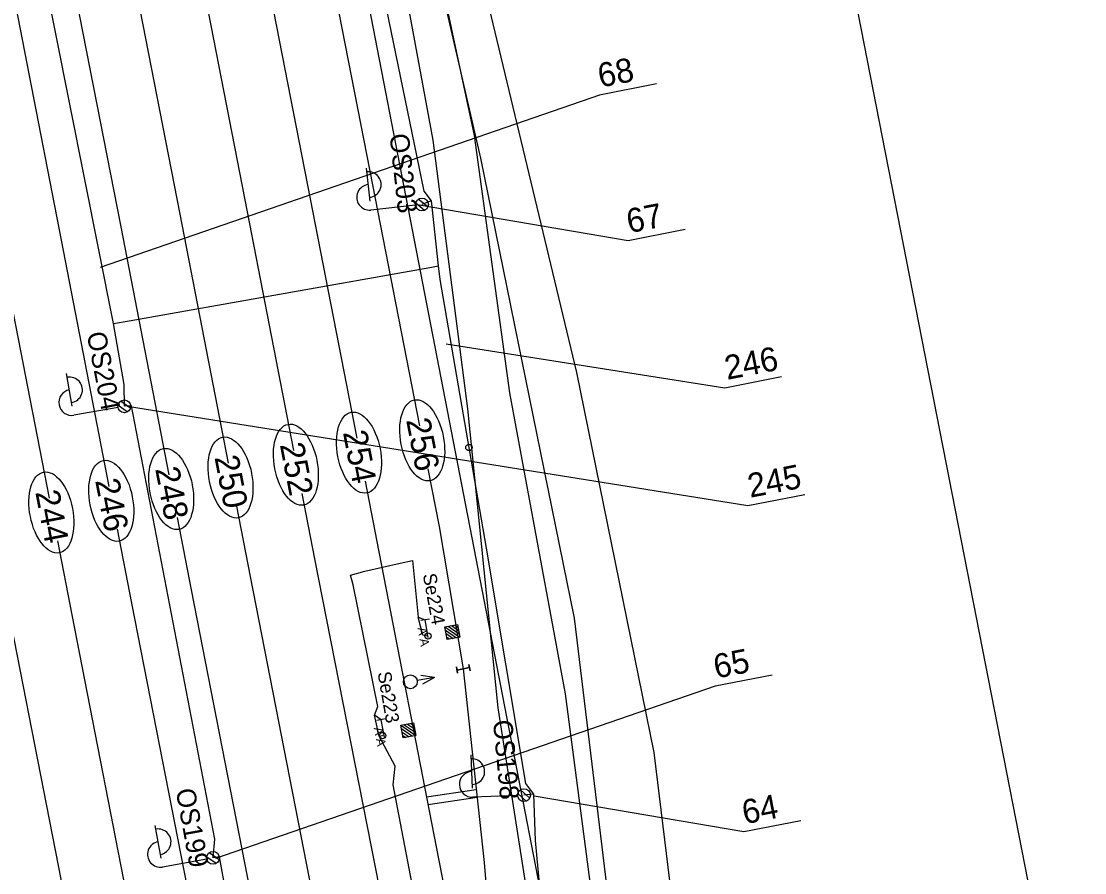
# Model space of a CAD drawing. Extents: x -545846 to -545044, y -1122650 to -1119108.
# Drawn here: x -545438.4 to -545355.4, y -1120101.7 to -1120035.3 of the extents above; entities that cross this region are included whole.
import ezdxf

# ---------------------------------------------------------------- set-up
doc = ezdxf.new("R2010")
doc.units = 0
for name, color, linetype in [('osvětlené plochy-hodnota-obrys', 7, 'Continuous'), ('so180602', 7, 'Continuous'), ('Vrstva 1', 7, 'Continuous'), ('Vrstva 10', 7, 'Continuous'), ('Vrstva 2', 7, 'Continuous'), ('Vrstva 25', 7, 'Continuous'), ('Vrstva 26', 7, 'Continuous'), ('Vrstva 27', 7, 'Continuous'), ('Vrstva 28 - zabzar', 7, 'Continuous'), ('Vrstva 3', 7, 'Continuous'), ('Vrstva 3 - Lisy - Pocitaci body', 7, 'Continuous'), ('Vrstva 35', 7, 'Continuous'), ('Vrstva 50', 7, 'Continuous'), ('Vrstva 51', 7, 'Continuous'), ('Vrstva 6 - Navesti', 7, 'Continuous'), ('Vrstva 62', 7, 'Continuous'), ('Vrstva 63', 7, 'Continuous'), ('Vrstva 7', 7, 'Continuous')]:
    doc.layers.add(name, color=color, linetype=linetype)

msp = doc.modelspace()

# ---------------------------------------------------------------- linework, layer by layer
at = {"layer": 'osvětlené plochy-hodnota-obrys'}
msp.add_lwpolyline([(-545520.965, -1119506.473), (-545505.641, -1119546.718), (-545397.928, -1120102.854)], dxfattribs=at)
at = {"layer": 'Vrstva 1'}
for points in [[(-545504.044, -1119675.302), (-545496.761, -1119712.409), (-545491.629, -1119738.674), (-545486.648, -1119764.117), (-545480.232, -1119797.005), (-545475.32, -1119822.26), (-545468.387, -1119857.799), (-545462.995, -1119885.431), (-545456.767, -1119917.378), (-545451.556, -1119944.051), (-545446.589, -1119969.431), (-545441.08, -1119997.674), (-545435.958, -1120023.865), (-545430.59, -1120051.32), (-545426.848, -1120070.672)], [(-545508.299, -1119678.306), (-545501.407, -1119713.415), (-545496.342, -1119739.402), (-545491.315, -1119765.122), (-545484.912, -1119797.951), (-545479.98, -1119823.279), (-545473.036, -1119858.809), (-545467.634, -1119886.502), (-545461.421, -1119918.347), (-545456.183, -1119945.113), (-545451.228, -1119970.493), (-545445.726, -1119998.726), (-545440.633, -1120024.762), (-545435.234, -1120052.378), (-545431.515, -1120071.58)], [(-545512.748, -1119680.062), (-545506.035, -1119714.374), (-545500.986, -1119740.293), (-545495.973, -1119766.064), (-545489.561, -1119798.976), (-545484.629, -1119824.29), (-545477.718, -1119859.753), (-545472.311, -1119887.471), (-545466.084, -1119919.335), (-545460.871, -1119946.033), (-545455.911, -1119971.399), (-545450.381, -1119999.679), (-545445.286, -1120025.774), (-545439.892, -1120053.375), (-545436.176, -1120072.488)], [(-545479.013, -1119699.159), (-545472.017, -1119734.995), (-545467.162, -1119760.064), (-545460.784, -1119792.802), (-545455.806, -1119818.056), (-545448.881, -1119853.558), (-545443.471, -1119881.241), (-545437.182, -1119913.498), (-545431.961, -1119940.155), (-545427.07, -1119965.242), (-545421.654, -1119993.224), (-545416.453, -1120019.834), (-545411.166, -1120046.971), (-545407.29, -1120066.864)], [(-545483.875, -1119700.285), (-545476.969, -1119735.847), (-545472.054, -1119761.115), (-545465.667, -1119793.733), (-545460.717, -1119819.165), (-545453.82, -1119854.518), (-545448.388, -1119882.153), (-545442.084, -1119914.383), (-545436.889, -1119940.99), (-545431.967, -1119966.286), (-545426.487, -1119994.319), (-545421.316, -1120020.9), (-545416.017, -1120048.076), (-545412.173, -1120067.814)], [(-545488.738, -1119701.593), (-545481.884, -1119736.765), (-545476.934, -1119762.146), (-545470.573, -1119794.819), (-545465.63, -1119820.165), (-545458.721, -1119855.563), (-545453.285, -1119883.263), (-545446.999, -1119915.438), (-545441.825, -1119942.011), (-545436.871, -1119967.298), (-545431.396, -1119995.476), (-545426.21, -1120021.976), (-545420.907, -1120049.228), (-545417.117, -1120068.777)], [(-545493.359, -1119705.369), (-545486.994, -1119737.853), (-545482.067, -1119763.163), (-545475.678, -1119795.841), (-545470.702, -1119821.285), (-545463.786, -1119856.655), (-545458.346, -1119884.478), (-545452.087, -1119916.549), (-545446.9, -1119943.082), (-545441.956, -1119968.347), (-545436.441, -1119996.626), (-545431.336, -1120022.902), (-545425.977, -1120050.333), (-545422.212, -1120069.769)], [(-545406.638, -1120070.213), (-545405.761, -1120074.712), (-545403.865, -1120085.82), (-545402.244, -1120100.926), (-545401.108, -1120114.416)], [(-545411.521, -1120071.164), (-545410.602, -1120075.884), (-545405.788, -1120100.651), (-545402.889, -1120115.448)], [(-545416.468, -1120072.127), (-545415.477, -1120077.238), (-545410.442, -1120102.898), (-545406.476, -1120123.181), (-545402.803, -1120143.109), (-545400.596, -1120164.815), (-545400.596, -1120181.651), (-545401.294, -1120192.943)], [(-545421.563, -1120073.119), (-545420.496, -1120078.625), (-545415.445, -1120104.449), (-545411.604, -1120124.066), (-545408, -1120142.528), (-545405.428, -1120157.949)], [(-545426.2, -1120074.022), (-545425.112, -1120079.647), (-545420.052, -1120105.492), (-545416.231, -1120125.122), (-545412.44, -1120144.547), (-545409.571, -1120160.021), (-545407.191, -1120182.024), (-545406.89, -1120192.899), (-545406.905, -1120196.005)], [(-545430.866, -1120074.93), (-545429.748, -1120080.704), (-545424.708, -1120106.469), (-545420.893, -1120126.013), (-545417.075, -1120145.62), (-545413.032, -1120166.33), (-545410.27, -1120183.003), (-545408.743, -1120196.073)], [(-545435.525, -1120075.838), (-545434.405, -1120081.599), (-545429.378, -1120107.352), (-545425.561, -1120126.873), (-545421.731, -1120146.486), (-545417.535, -1120168.115), (-545415.459, -1120178.849), (-545413.975, -1120187.465)], [(-545440.228, -1120076.753), (-545439.131, -1120082.41), (-545434.086, -1120108.231), (-545430.241, -1120127.909), (-545426.423, -1120147.488), (-545422.179, -1120169.181), (-545418.498, -1120187.953)]]:
    msp.add_lwpolyline(points, dxfattribs=at)
for centre in [(-545407.071, -1120067.99), (-545412.004, -1120068.946), (-545416.929, -1120069.89), (-545422.027, -1120070.887), (-545426.656, -1120071.785), (-545431.335, -1120072.71), (-545436.005, -1120073.616)]:
    msp.add_ellipse(centre, major_axis=(0.614, -3.151), ratio=0.521067, dxfattribs=at)
at = {"layer": 'Vrstva 10'}
msp.add_line((-545554.372, -1119108.31), (-545292.195, -1120447.895), dxfattribs=at)
at = {"layer": 'Vrstva 25'}
for p, q in [((-545411.145, -1120049.319), (-545411.427, -1120046.735)), ((-545406.633, -1120049.772), (-545407.379, -1120049.173)), ((-545407.59, -1120049.636), (-545411.069, -1120050.015)), ((-545406.896, -1120050.041), (-545407.582, -1120049.49)), ((-545434.373, -1120065.333), (-545434.824, -1120062.772)), ((-545429.84, -1120065.489), (-545430.624, -1120064.939)), ((-545430.804, -1120065.416), (-545434.251, -1120066.022)), ((-545430.085, -1120065.774), (-545430.806, -1120065.27)), ((-545403.159, -1120095.138), (-545403.262, -1120092.54)), ((-545399.634, -1120095.699), (-545403.131, -1120095.838)), ((-545398.969, -1120096.151), (-545399.615, -1120095.554)), ((-545398.688, -1120095.9), (-545399.391, -1120095.251)), ((-545427.451, -1120100.6), (-545427.916, -1120098.042)), ((-545423.882, -1120100.662), (-545427.325, -1120101.288)), ((-545423.161, -1120101.017), (-545423.884, -1120100.516)), ((-545422.917, -1120100.73), (-545423.704, -1120100.185))]:
    msp.add_line(p, q, dxfattribs=at)
for centre in [(-545407.093, -1120049.582), (-545407.093, -1120049.582), (-545430.312, -1120065.329), (-545430.312, -1120065.329), (-545399.134, -1120095.679), (-545399.134, -1120095.679), (-545423.39, -1120100.573), (-545423.39, -1120100.573)]:
    msp.add_circle(centre, 0.5, dxfattribs=at)
for centre, start, end in [((-545411.274, -1120048.026), 275.51472, 96.91987), ((-545411.178, -1120049.021), 96.2173, 276.2173), ((-545434.586, -1120064.051), 279.2814, 100.68655), ((-545434.425, -1120065.038), 99.98397, 279.98397), ((-545403.198, -1120093.839), 271.57038, 92.97552), ((-545403.171, -1120094.838), 92.27295, 272.27295), ((-545427.671, -1120099.318), 279.60078, 101.00593), ((-545427.504, -1120100.305), 100.30335, 280.30335)]:
    msp.add_arc(centre, 1, start, end, dxfattribs=at)
at = {"layer": 'Vrstva 26'}
for points in [[(-545416.465, -1119997.823), (-545416.35, -1120000.23), (-545412.42, -1120021.84), (-545406.945, -1120048.545), (-545406.368, -1120049.305), (-545407.093, -1120049.582)], [(-545419.408, -1120146.037), (-545419.607, -1120144.864), (-545417.984, -1120144.721), (-545414.909, -1120144.169), (-545418.585, -1120124.133), (-545422.884, -1120100.485), (-545423.39, -1120100.573), (-545423.256, -1120099.117), (-545429.764, -1120065.297), (-545430.312, -1120065.329), (-545430.316, -1120063.627), (-545431.155, -1120058.861), (-545436.816, -1120030.49), (-545441.618, -1120005.901), (-545442.588, -1120002.676)], [(-545406.368, -1120049.305), (-545405.816, -1120054.372), (-545405.7, -1120055.44), (-545402.08, -1120076.41), (-545399.016, -1120094.766), (-545398.394, -1120095.592), (-545399.134, -1120095.679)], [(-545431.155, -1120058.861), (-545429.949, -1120058.671), (-545406.47, -1120054.49), (-545405.816, -1120054.372)], [(-545431.155, -1120058.861), (-545429.949, -1120058.671), (-545406.47, -1120054.49)], [(-545398.394, -1120095.592), (-545398.25, -1120099.22), (-545395.83, -1120125.2), (-545394.03, -1120140.6), (-545393.889, -1120142.062), (-545393.145, -1120142.85), (-545393.979, -1120142.941)]]:
    msp.add_lwpolyline(points, dxfattribs=at)
at = {"layer": 'Vrstva 27'}
for p, q in [((-545406.616, -1120083.285), (-545406.624, -1120083.235)), ((-545410.155, -1120091.055), (-545410.165, -1120091.005))]:
    msp.add_line(p, q, dxfattribs=at)
for centre in [(-545406.62, -1120083.26), (-545410.16, -1120091.03)]:
    msp.add_circle(centre, 0.25, dxfattribs=at)
at = {"layer": 'Vrstva 28 - zabzar'}
for p, q in [((-545410.27, -1120089.79), (-545410.79, -1120089.43)), ((-545410.42, -1120091.07), (-545410.16, -1120091.03))]:
    msp.add_line(p, q, dxfattribs=at)
for points in [[(-545400.44, -1120142.19), (-545400.3, -1120141.39), (-545401.05, -1120141.27), (-545401.69, -1120138.45), (-545401.85, -1120137.24), (-545402.58, -1120132.35), (-545404.02, -1120124.35), (-545404.09, -1120123.79), (-545405.15, -1120117.55), (-545405.56, -1120115.55), (-545405.9, -1120112.13), (-545406.95, -1120107.38), (-545409.35, -1120094.87), (-545409.17, -1120093.41), (-545410.42, -1120091.07), (-545410.79, -1120089.43), (-545410.53, -1120088.75), (-545412.47, -1120079.27), (-545412.67, -1120078.51), (-545411.56, -1120078.19), (-545408.79, -1120077.57), (-545407.82, -1120077.37), (-545407.38, -1120081.8), (-545406.84, -1120082)], [(-545406.62, -1120083.26), (-545407.02, -1120083.19), (-545407.38, -1120081.8)]]:
    msp.add_lwpolyline(points, dxfattribs=at)
at = {"layer": 'Vrstva 3'}
for p, q in [((-545404.308, -1120086.161), (-545404.404, -1120085.67)), ((-545404.404, -1120085.671), (-545404.308, -1120086.161)), ((-545403.374, -1120085.724), (-545404.356, -1120085.916)), ((-545404.356, -1120085.916), (-545403.374, -1120085.724)), ((-545403.422, -1120085.479), (-545403.326, -1120085.969)), ((-545403.326, -1120085.97), (-545403.422, -1120085.479)), ((-545406.1, -1120086.506), (-545407.46, -1120086.738)), ((-545406.1, -1120086.506), (-545407.178, -1120086.34)), ((-545406.1, -1120086.506), (-545407.062, -1120087.02))]:
    msp.add_line(p, q, dxfattribs=at)
msp.add_circle((-545407.995, -1120086.828), 0.542, dxfattribs=at)
at = {"layer": 'Vrstva 3 - Lisy - Pocitaci body'}
for p, q in [((-545404.777, -1120082.446), (-545404.235, -1120082.83)), ((-545404.516, -1120082.402), (-545404.28, -1120082.569)), ((-545405.3, -1120082.535), (-545404.146, -1120083.353)), ((-545405.255, -1120082.797), (-545404.407, -1120083.397)), ((-545405.211, -1120083.058), (-545404.669, -1120083.442)), ((-545405.039, -1120082.491), (-545404.19, -1120083.092)), ((-545405.166, -1120083.32), (-545404.93, -1120083.487)), ((-545408.737, -1120090.23), (-545407.565, -1120091.021)), ((-545408.686, -1120090.49), (-545407.825, -1120091.071)), ((-545408.636, -1120090.751), (-545408.085, -1120091.122)), ((-545408.477, -1120090.179), (-545407.615, -1120090.761)), ((-545408.216, -1120090.129), (-545407.666, -1120090.5)), ((-545407.956, -1120090.078), (-545407.716, -1120090.24)), ((-545408.585, -1120091.011), (-545408.345, -1120091.173))]:
    msp.add_line(p, q, dxfattribs=at)
for points in [[(-545404.314, -1120082.367), (-545404.146, -1120083.353), (-545405.132, -1120083.521), (-545405.3, -1120082.535)], [(-545407.755, -1120090.039), (-545407.565, -1120091.021), (-545408.546, -1120091.212), (-545408.737, -1120090.23)]]:
    msp.add_lwpolyline(points, close=True, dxfattribs=at)
at = {"layer": 'Vrstva 35'}
msp.add_lwpolyline([(-545412.67, -1120078.51), (-545411.56, -1120078.19), (-545408.79, -1120077.57), (-545407.82, -1120077.37)], dxfattribs=at)
at = {"layer": 'Vrstva 50'}
msp.add_line((-545403.45, -1120068.543), (-545403.4, -1120068.543), dxfattribs=at)
msp.add_circle((-545403.425, -1120068.543), 0.25, dxfattribs=at)
at = {"layer": 'Vrstva 51'}
for points in [[(-545474.36, -1119688.255), (-545466.579, -1119732.11), (-545462.51, -1119756.655), (-545455.831, -1119789.993), (-545450.917, -1119814.901), (-545443.717, -1119850.687), (-545439.158, -1119879.07), (-545432.576, -1119913.186), (-545426.875, -1119936.671), (-545422.743, -1119962.506), (-545418.335, -1119990.017), (-545411.428, -1120016.49), (-545406.245, -1120044.568), (-545403.533, -1120065.521), (-545401.184, -1120088.868), (-545397.016, -1120115.443), (-545395.196, -1120135.679), (-545394.057, -1120143.256), (-545386.488, -1120187.748)], [(-545470.7, -1119687.746), (-545464.137, -1119731.581), (-545459.972, -1119755.883), (-545452.874, -1119789.329), (-545448.102, -1119814.108), (-545441.139, -1119850.218), (-545435.794, -1119878.29), (-545429.367, -1119912.848), (-545423.033, -1119935.797), (-545419.144, -1119961.66), (-545414.863, -1119988.762), (-545403.007, -1120044.19), (-545400.258, -1120064.288), (-545395.915, -1120087.784), (-545392.445, -1120114.396), (-545391.179, -1120135.428), (-545389.936, -1120142.632), (-545383.231, -1120188.01)]]:
    msp.add_lwpolyline(points, dxfattribs=at)
at = {"layer": 'Vrstva 6 - Navesti'}
for p, q in [((-545406.495, -1120081.941), (-545407.185, -1120082.059)), ((-545406.607, -1120083.366), (-545406.84, -1120082)), ((-545409.926, -1120089.723), (-545410.614, -1120089.857)), ((-545410.006, -1120091.151), (-545410.27, -1120089.79))]:
    msp.add_line(p, q, dxfattribs=at)
at = {"layer": 'Vrstva 62'}
for points in [[(-545423.216, -1119917.425), (-545425.626, -1119923.902), (-545421.66, -1119936.357), (-545417.987, -1119968.93), (-545408.636, -1120019.429), (-545402.531, -1120045.967), (-545395.226, -1120081.877), (-545392.76, -1120102.085), (-545388.408, -1120138.929), (-545385.069, -1120161.88), (-545380.677, -1120185.181), (-545377.636, -1120190.956), (-545375.6, -1120199.999)], [(-545371.516, -1120199.999), (-545381.387, -1120154.552), (-545388.984, -1120092.348), (-545395.017, -1120062.684), (-545403.862, -1120025.812), (-545411.302, -1119985.582), (-545417.876, -1119943.114), (-545420.973, -1119925.302), (-545417.81, -1119919.208)]]:
    msp.add_lwpolyline(points, dxfattribs=at)
at = {"layer": 'Vrstva 63'}
for p, q in [((-545388.788, -1120040.176), (-545393.232, -1120041.04)), ((-545393.232, -1120041.04), (-545432.195, -1120054.508)), ((-545391.007, -1120052.41), (-545407.3, -1120049.643)), ((-545386.563, -1120051.546), (-545391.007, -1120052.41)), ((-545383.472, -1120063.908), (-545405.197, -1120060.483)), ((-545379.027, -1120063.044), (-545383.472, -1120063.908)), ((-545379.027, -1120063.044), (-545383.472, -1120063.908)), ((-545379.027, -1120063.044), (-545383.472, -1120063.908)), ((-545381.67, -1120073.112), (-545430.077, -1120065.359)), ((-545377.226, -1120072.248), (-545381.67, -1120073.112)), ((-545377.226, -1120072.248), (-545381.67, -1120073.112)), ((-545377.226, -1120072.248), (-545381.67, -1120073.112)), ((-545379.76, -1120086.303), (-545384.205, -1120087.167)), ((-545384.205, -1120087.167), (-545423.193, -1120100.63)), ((-545381.98, -1120098.537), (-545398.345, -1120095.767)), ((-545377.535, -1120097.673), (-545381.98, -1120098.537))]:
    msp.add_line(p, q, dxfattribs=at)
at = {"layer": 'Vrstva 7'}
for p, q in [((-545406.727, -1120095.82), (-545402.854, -1120095.237)), ((-545406.612, -1120096.41), (-545402.79, -1120095.834))]:
    msp.add_line(p, q, dxfattribs=at)

# ---------------------------------------------------------------- texts
at = {"layer": 'so180602'}
for s, p in [('68', (-545393.171, -1120040.46)), ('67', (-545390.932, -1120051.827)), ('246', (-545383.283, -1120063.272)), ('245', (-545381.482, -1120072.476)), ('65', (-545384.144, -1120086.587)), ('64', (-545381.918, -1120097.956))]:
    msp.add_text(s, height=1.875, rotation=10.99553, dxfattribs=at).set_placement(p)
at = {"layer": 'Vrstva 2'}
for s, p in [('256', (-545408.332, -1120066.405)), ('254', (-545413.264, -1120067.365)), ('252', (-545418.186, -1120068.322)), ('250', (-545423.285, -1120069.314)), ('248', (-545427.914, -1120070.215)), ('246', (-545432.596, -1120071.126)), ('244', (-545437.265, -1120072.034))]:
    msp.add_text(s, height=1.875, rotation=280.91172, dxfattribs=at).set_placement(p)
at = {"layer": 'Vrstva 25'}
for s, rotation, p in [('OS203', 276.2173, (-545409.622, -1120044.12)), ('OS204', 280.89231, (-545433.258, -1120059.652)), ('OS198', 275.32166, (-545401.552, -1120089.872)), ('OS199', 280.30335, (-545426.311, -1120095.282))]:
    msp.add_text(s, height=1.5, rotation=rotation, dxfattribs=at).set_placement(p)
at = {"layer": 'Vrstva 6 - Navesti'}
for s, height, rotation, p in [('Se224', 1.05, 280.40718, (-545407.033, -1120078.463)), ('  A A ', 0.7, 279.68634, (-545407.53, -1120082.118)), ('Se223', 1.05, 279.76826, (-545410.561, -1120086.119)), ('  A A ', 0.7, 280.99952, (-545410.957, -1120089.924))]:
    msp.add_text(s, height=height, rotation=rotation, dxfattribs=at).set_placement(p)

doc.saveas('drawing.dxf')
